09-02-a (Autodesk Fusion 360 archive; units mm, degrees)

design "09-02-a" references "09-02-KOTEI", "09-02-KADOU"
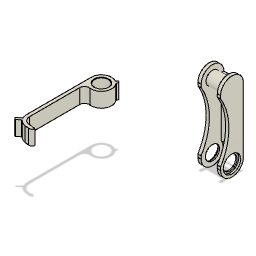
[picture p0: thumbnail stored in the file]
component_insert "コンポーネントの挿入1"
ground "固定1"
component_insert "コンポーネントの挿入3"
ground "固定4"

design "09-02-KOTEI"
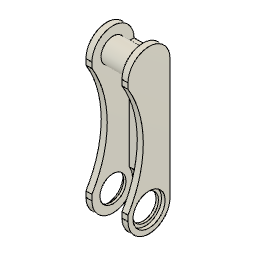
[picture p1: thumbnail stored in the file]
sketch "スケッチ1" plane through (0, 0, 0) normal (1, 0, 0) x axis (0, 0, -1)
  circle C1 centre (0, 40) radius 4
  point P1 (0, 0)
  point P2 (0, 40)
  vertical P1 P2
  dimension "d1" diameter C1 = 8
  dimension "d29" distance P1 P2 = 40
extrude "押し出し1" new body sketch "スケッチ1" + "スケッチ5" profile of S1:C1 distance 10
sketch "スケッチ2" plane through (5, 0, 0) normal (1, 0, 0) x axis (0, 0, -1)
  line L1 (-7, 0) -> (-7, 40)
  line L2 (7, 40) -> (7, 0)
  line L3 (0, 0) -> (0, 40)
  circle C1 centre (0, 40) radius 4
  arc A1 centre (0, 0) radius 7 clockwise from (7, 0) to (-7, 0)
  arc A2 centre (0, 40) radius 7 clockwise from (-7, 40) to (7, 40)
  point P7 (0, 40)
  point P9 (0, 40)
  point P8 (0, 0)
  tangent L1 A1
  tangent A1 L2
  parallel L1 L2
  tangent L2 A2
  tangent L1 A2
  vertical L3
  coincident P7 P9
  concentric C1 A2
  dimension "d4" radius A2 = 7
  dimension "d5" distance P7 P8 = 40
extrude "押し出し2" add sketch "スケッチ2" profile of C1 L1 A1 L2 A2 along normal blind 2
mirror "ミラー" sketch "スケッチ5" mirrorStitchTolerance 0.1
sketch "スケッチ3" plane through (0, 0, 0) normal (1, 0, 0) x axis (0, 0, -1)
  line L1 (7, 40) -> (5.4, 40)
  line L2 (7, 0) -> (7, 40)
  line L3 (5.4, 0) -> (7, 0)
  line L4 (5.4, 40) -> (5.4, 0)
  point P3 (7, 40)
  point P6 (7, 40)
  point P4 (7, 0)
  point P7 (7, 0)
  horizontal L1
  vertical L2
  horizontal L3
  vertical L4
  coincident P3 P6
  coincident P4 P7
  dimension "d10" distance L2 L4 = 1.6
extrude "押し出し3" add sketch "スケッチ3" distance 10
sketch "スケッチ4" plane through (0, 0, 0) normal (1, 0, 0) x axis (0, 0, -1)
  circle C1 centre (-36.9324, 20) radius 35
  arc A1 centre (0, 40) radius 7 clockwise from (-7, 40) to (7, 40)
  arc A2 centre (0, 0) radius 7 clockwise from (7, 0) to (-7, 0)
  tangent C1 A1
  tangent C1 A2
  dimension "d13" diameter C1 = 70
extrude "押し出し4" cut sketch "スケッチ4" profile of C1 no distance stored
sketch "スケッチ5" plane through (0, 0, 0) normal (1, 0, 0) x axis (0, 0, -1)
  circle C1 centre (0, 0) radius 6.5
  arc A1 centre (0, 0) radius 7 clockwise from (7, 0) to (-7, 0)
  concentric C1 A1
  dimension "d15" diameter C1 = 13
extrude "押し出し5" cut sketch "スケッチ5" profile of C1 distance 10
chamfer "面取り" distance 0.2
hole "穴1" HoleDepth 2 HoleDiameter 8.7 TipAngle 118 CBDepth 1.2 CBDiameter 10.7
hole "穴2" HoleDepth 2 HoleDiameter 8.7 TipAngle 118 CBDepth 1.2 CBDiameter 10.7
joint_origin "JointOrigin1" sketch "スケッチ5" OffsetX 0 OffsetY 0 OffsetZ 0 AngleZ 0

design "09-02-KADOU"
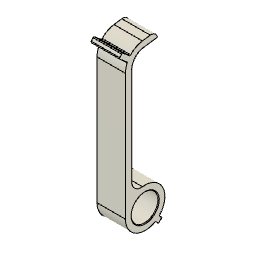
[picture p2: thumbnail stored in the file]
sketch "スケッチ1" plane through (0, 0, 0) normal (1, 0, 0) x axis (0, 0, -1)
  circle C1 centre (0, 0) radius 6.25
  point P1 (0, 0)
  point P2 (0, 0)
  coincident P1 P2
  dimension "d1" diameter C1 = 12.5
extrude "押し出し1" new body sketch "スケッチ1" distance 9
sketch "スケッチ2" plane through (0, 0, 0) normal (1, 0, 0) x axis (0, 0, -1)
  line L1 (-4.25, 0) -> (-4.25, 40)
  line L2 (-6.25, 0) -> (-4.25, 0)
  line L3 (-6.25, 40) -> (-6.25, 0)
  line L4 (3.8647, 44.8349) -> (-0.5915, 44.2086)
  line L5 (3.5864, 46.8155) -> (3.8647, 44.8349)
  line L6 (-0.8698, 46.1892) -> (3.5864, 46.8155)
  circle C1 centre (0, 0) radius 6.25
  arc A1 centre (0, 40) radius 4.25 clockwise from (-4.25, 40) to (-0.5915, 44.2086)
  arc A2 centre (0, 40) radius 6.25 clockwise from (-6.25, 40) to (-0.8698, 46.1892)
  point P1 (0, 0)
  point P8 (0, 40)
  point P12 (0, 40)
  vertical L1
  horizontal L2
  vertical L3
  coincident P1 L2
  tangent L3 C1
  perpendicular L4 L5
  perpendicular L5 L6
  coincident P8 P12
  vertical P1 P8
  tangent L1 A1
  tangent A1 L4
  tangent L3 A2
  dimension "d5" distance L1 L3 = 2
  dimension "d18" distance L4 L6 = 2
  dimension "d21" distance P8 L5 = 4.5
  dimension "d22" angle L1 L4 = 98
  dimension "d54" distance P1 P12 = 40
extrude "押し出し2" add sketch "スケッチ2" profile of L1 L3 C1 distance 9
sketch "スケッチ4" plane through (0, 0, 0) normal (1, 0, 0) x axis (0, 0, -1)
  line L1 (5.3033, -5.3033) -> (0, 0)
  line L2 (4.2426, -6.364) -> (5.3033, -5.3033)
  line L3 (-1.0607, -1.0607) -> (4.2426, -6.364)
  line L4 (0, 0) -> (-1.0607, -1.0607)
  line L5 (-22.5, 0) -> (-1.75, 0)
  point P1 (0, 0)
  point P2 (0, 0)
  perpendicular L1 L2
  parallel L1 L3
  parallel L2 L4
  coincident P1 P2
  dimension "d24" angle L1 L5 = 45
  dimension "d25" distance L2 L4 = 7.5
  dimension "d26" distance L1 L3 = 1.5
extrude "押し出し4" add sketch "スケッチ4" profile of L1 L2 L3 L4 distance 9
joint_origin "JointOrigin1" OffsetX 0 OffsetY 0 OffsetZ 0 AngleZ 0
sketch "スケッチ5" plane through (0, 0, 0) normal (1, 0, 0) x axis (0, 0, -1)
  line L1 (0, 40) -> (-7.2774, 46.1065)
  line L2 (-0.9642, 38.8509) -> (0, 40)
  line L3 (-8.2416, 44.9574) -> (-0.9642, 38.8509)
  line L4 (-7.2774, 46.1065) -> (-8.2416, 44.9574)
  line L5 (0, 22.5) -> (0, 1.75)
  arc A1 centre (0, 40) radius 4.25 clockwise from (-4.25, 40) to (-0.5915, 44.2086)
  point P3 (0, 40)
  point P8 (0, 40)
  perpendicular L1 L2
  parallel L1 L3
  parallel L2 L4
  coincident P3 P8
  dimension "d33" angle L1 L5 = 50
  dimension "d34" distance L1 L3 = 1.5
  dimension "d35" distance L2 L4 = 9.5
extrude "押し出し5" add sketch "スケッチ5" profile of L1 L3 L4 A1 distance 9
fillet "フィレット3" radius 2
sketch "スケッチ6" plane through (0, 43.4339, 6.1042) normal (0, -0.9903, -0.1392) x axis (-1, 0, 0)
  line L1 (-4.5, 10.0669) -> (4.5, 10.0669)
  line L2 (-4.5, 5.5669) -> (-4.5, 10.0669)
  line L3 (4.5, 5.5669) -> (-4.5, 5.5669)
  line L4 (4.5, 10.0669) -> (4.5, 5.5669)
  circle C1 centre (0, 8.0669) radius 0.75
  point P1 (0, 0)
  point P6 (0, 8.0669)
  vertical P1 P6
  dimension "d40" distance L1 P6 = 2
  dimension "d41" diameter C1 = 1.5
extrude "押し出し6" add sketch "スケッチ6" profile of C1 along normal blind 0.7
fillet "フィレット4" radius 0.6
fillet "フィレット5" radius 3
fillet "フィレット6" radius 0.3
hole "穴" HoleDepth 9 HoleDiameter 8.5 TipAngle 118
chamfer "面取り" distance 0.2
